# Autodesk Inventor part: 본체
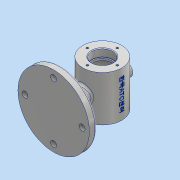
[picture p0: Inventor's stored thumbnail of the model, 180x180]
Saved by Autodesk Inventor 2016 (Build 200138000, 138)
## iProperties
Created: 2018-12
Part Number: 본체
Material: 알루미늄 6061
Document SubType Name: Modeling
Designer: 3sil_cad018
Density: 2.7 g/cm^3
Appearance: 알루미늄 - 평지
Mass: 683.279 g
Surface Area: 559.795 cm^2
Volume: 253.066 cm^3
Author: 3sil_cad018
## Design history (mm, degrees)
sketch "스케치1"
  geometry: C1 r 30 at (0, 0); 1 further point
  constraints: 1 centre point, 1 coincident
  dimensions: "d0" = 60 diameter of C1
extrude "돌출1" new body sketch "스케치1" distance "d1" = 70; taper "d2" = 0 deg
node "작업 평면2"
sketch "스케치5"
  geometry: L1 (30, 70)-(-30, 70) reference; L2 (-30, 0)-(30, 0) reference; L3 (30, 0)-(30, 70) reference; L4 (-30, 0)-(-30, 70) reference; C1 r 55 at (0, 35); 3 further points
  constraints: 2 midpoint, 1 centre point, 1 horizontal alignment, 1 vertical alignment
  dimensions: "d8" = 110 diameter of C1
extrude "돌출3" join sketch "스케치5" distance "d9" = 11; taper "d10" = 0 deg
sketch "스케치6"
  geometry: L1 (-64, -20)-(-64, 90) reference; L2 (-64, 35)-(-14, 35); L3 (-14, 35)-(-14, 47); L4 (-14, 47)-(-52.478, 47); L5 (-52.478, 47)-(-64, 90); L6 (-64, 90)-(-64, 35); L7 (-75, 90)-(-64, 90) reference; 1 further point
  constraints: 10 end point, 2 perpendicular, 1 collinear, 1 horizontal, 1 midpoint
  dimensions: "d11" = 24 diameter of L4 L2; "d12" = 75 deg angle of L7 L5; "d13" = 50 distance of L2.start L2.end
revolve "회전1" sketch "스케치6" stored, may be unused: angle "d14" = 90 deg
fillet "모깎기1" dims "d15" = 3
sketch "스케치7"
  geometry: L1 (30, 70)-(-30, 70) reference; L2 (16, 70)-(16, 58); L3 (16, 58)-(14, 58); L4 (14, 58)-(14, 55); L5 (14, 55)-(25, 55); L6 (25, 55)-(25, 15); L7 (25, 15)-(14, 15); L8 (14, 15)-(14, 12); L9 (14, 12)-(16, 12); L10 (16, 12)-(16, 0); L11 (16, 0)-(0, 0); L12 (-30, 0)-(30, 0) reference; L13 (0, 0)-(0, 70); L14 (0, 70)-(16, 70); 3 further points
  constraints: 24 end point, 7 perpendicular, 5 point on line, 4 midpoint, 1 collinear, 1 horizontal, 1 vertical, 1 vertical alignment
  dimensions: "d16" = 12 distance of L2.start L2.end; "d17" = 40 distance of L5.end L6.end; "d18" = 3 distance of L3.end L4.end; "d19" = 12 distance of L9.end L10.end; "d20" = 32 diameter of L2 L13; "d21" = 28 diameter of L4 L13; "d22" = 50 diameter of L6 L13
revolve "회전2" sketch "스케치7" stored, may be unused: angle "d23" = 90 deg
fillet "모깎기2" dims "d24" = 3
node "작업 평면3"
sketch "스케치8"
  geometry: L1 (30, 35)-(-30, 35) reference; L2 (-30, -35)-(30, -35) reference; L3 (-30, -35)-(-30, 35) reference; C1 r 10 at (0, 0); 4 further points
  constraints: 2 midpoint, 1 centre point, 1 horizontal alignment, 1 vertical alignment, 1 other
  dimensions: "d26" = 20 diameter of C1
extrude "돌출4" join sketch "스케치8" stored distance "d27" = 10; taper "d28" = 0 deg
sketch "스케치9"
  geometry: C1 r 5 at (0, 0); C2 r 10 at (0, 0) reference; 1 further point
  constraints: 1 centre point, 1 coincident
  dimensions: "d29" = 10 diameter of C1
extrude "돌출5" cut sketch "스케치9" distance "d30" = 20; taper "d31" = 0 deg
sketch "스케치10"
  geometry: C1 r 55 at (0, 0) reference; 2 further points
  constraints: 1 vertical alignment
  dimensions: "d32" = 44 distance of point (0, 44) C1.centre
hole "구멍1" sketch "스케치10" at (0, 44) diameter "d33" = 9; stored, may be unused: countersink angle "d37" = 90 deg, drill point angle "d39" = 118 deg; dims "d34" = 6, "d35" = 4, "d36" = 2, "d38" = 8
node "작업 평면4"
sketch "스케치11"
  geometry: C1 r 7 at (0, 43.54); 4 further points
  constraints: 2 vertical alignment, 1 centre point, 1 coincident, 1 horizontal alignment, 2 other
  dimensions: "d41" = 14 diameter of C1
extrude "돌출6" cut sketch "스케치11" distance "d42" = 20; taper "d43" = 0 deg
sketch "스케치12"
  geometry: C1 r 25 at (0, 0) reference; C2 r 30 at (0, 0) reference; 2 further points
  constraints: 1 vertical alignment
  dimensions: "d47" = 23 distance of point (0, 0) point (0, 23)
hole "구멍2" sketch "스케치12" at (0, 23) diameter "d48" = 3.242; stored, may be unused: countersink angle "d52" = 90 deg, drill point angle "d54" = 118 deg; dims "d49" = 8, "d50" = 4, "d51" = 2, "d53" = 10
node "작업 평면5"
node "작업 평면6"
node "작업 평면8"
sketch "스케치16"
  geometry: L1 (30, 0)-(30, 70) reference; L2 (30, 70)-(-30, 70) reference; 2 further points
  constraints: 1 other
  dimensions: "d62" = 30 distance from line of point (0, 35) L1; "d63" = 35 distance from line of point (0, 35) L2
feature "엠보싱1" sketch "스케치16" dims "d64" = 0.5, "d65" = 0
fillet "모깎기3" dims "d66" = 3
fillet "모깎기4" dims "d67" = 0.3
chamfer "모따기1" distance "d68" = 1; stored, may be unused: second distance "d69" = 2, angle "d70" = 45 deg
chamfer "모따기2" distance "d71" = 1; stored, may be unused: second distance "d72" = 2, angle "d73" = 45 deg
node "솔리드1"
pattern_circular "원형 패턴1" dims angle "d45" = 360 deg
pattern_circular "원형 패턴2" dims angle "d56" = 360 deg
mirror "대칭1"
node "투영된 루프2"
node "투영된 루프3"
node "투영된 루프4"
node "투영된 루프5"
other parameters: "d7" = -75, "d25" = -112, "d58" = -35, "d61" = 62.25
